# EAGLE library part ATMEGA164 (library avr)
MICROCONTROLLER 16 Kbytes FLASH 1 Kbytes SRAM 512 Bytes EEPROM DUAL USART 8-channel 10 bit ADC
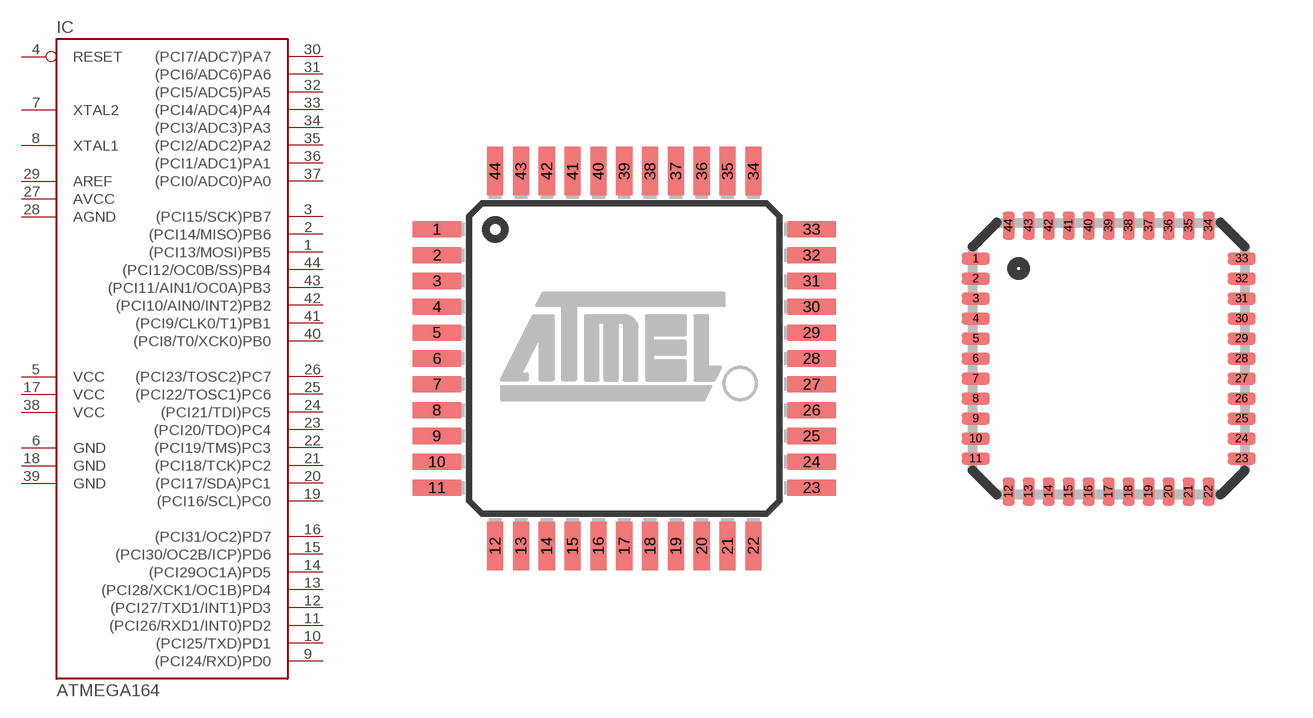
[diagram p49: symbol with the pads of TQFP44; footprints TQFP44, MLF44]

Designator prefix IC

## ATMEGA164-20A, ATMEGA164V-10A  [TQFP44]
1  (PCI13/MOSI)PB5
2  (PCI14/MISO)PB6
3  (PCI15/SCK)PB7
4  RESET  in
5  VCC  pwr
6  GND  pwr
7  XTAL2
8  XTAL1
9  (PCI24/RXD)PD0
10  (PCI25/TXD)PD1
11  (PCI26/RXD1/INT0)PD2
12  (PCI27/TXD1/INT1)PD3
13  (PCI28/XCK1/OC1B)PD4
14  (PCI29OC1A)PD5
15  (PCI30/OC2B/ICP)PD6
16  (PCI31/OC2)PD7
17  VCC  pwr
18  GND  pwr
19  (PCI16/SCL)PC0
20  (PCI17/SDA)PC1
21  (PCI18/TCK)PC2
22  (PCI19/TMS)PC3
23  (PCI20/TDO)PC4
24  (PCI21/TDI)PC5
25  (PCI22/TOSC1)PC6
26  (PCI23/TOSC2)PC7
27  AVCC  pwr
28  AGND  pwr
29  AREF  pwr
30  (PCI7/ADC7)PA7
31  (PCI6/ADC6)PA6
32  (PCI5/ADC5)PA5
33  (PCI4/ADC4)PA4
34  (PCI3/ADC3)PA3
35  (PCI2/ADC2)PA2
36  (PCI1/ADC1)PA1
37  (PCI0/ADC0)PA0
38  VCC  pwr
39  GND  pwr
40  (PCI8/T0/XCK0)PB0
41  (PCI9/CLK0/T1)PB1
42  (PCI10/AIN0/INT2)PB2
43  (PCI11/AIN1/OC0A)PB3
44  (PCI12/OC0B/SS)PB4

## ATMEGA164-20M, ATMEGA164V-10M  [MLF44]
Pads as for TQFP44

## Footprint TQFP44 (pad centres in mm)
Thin Plasic Quad Flat Package
smd 1.5 x 0.5: 1 -5.8,4; 2 -5.8,3.2; 3 -5.8,2.4; 4 -5.8,1.6; 5 -5.8,0.8; 6 -5.8,0; 7 -5.8,-0.8; 8 -5.8,-1.6; 9 -5.8,-2.4; 10 -5.8,-3.2; 11 -5.8,-4; 23 5.8,-4; 24 5.8,-3.2; 25 5.8,-2.4; 26 5.8,-1.6; 27 5.8,-0.8; 28 5.8,0; 29 5.8,0.8; 30 5.8,1.6; 31 5.8,2.4; 32 5.8,3.2; 33 5.8,4
smd 0.5 x 1.5: 12 -4,-5.8; 13 -3.2,-5.8; 14 -2.4,-5.8; 15 -1.6,-5.8; 16 -0.8,-5.8; 17 0,-5.8; 18 0.8,-5.8; 19 1.6,-5.8; 20 2.4,-5.8; 21 3.2,-5.8; 22 4,-5.8; 34 4,5.8; 35 3.2,5.8; 36 2.4,5.8; 37 1.6,5.8; 38 0.8,5.8; 39 0,5.8; 40 -0.8,5.8; 41 -1.6,5.8; 42 -2.4,5.8; 43 -3.2,5.8; 44 -4,5.8

## Footprint MLF44 (pad centres in mm)
44M1 Micro Lead Frame package (MLF)
smd 0.7 x 0.3: 1 -3.325,2.5; 2 -3.325,2; 3 -3.325,1.5; 4 -3.325,1; 5 -3.325,0.5; 6 -3.325,0; 7 -3.325,-0.5; 8 -3.325,-1; 9 -3.325,-1.5; 10 -3.325,-2; 11 -3.325,-2.5; 23 3.325,-2.5; 24 3.325,-2; 25 3.325,-1.5; 26 3.325,-1; 27 3.325,-0.5; 28 3.325,0; 29 3.325,0.5; 30 3.325,1; 31 3.325,1.5; 32 3.325,2; 33 3.325,2.5
smd 0.3 x 0.7: 12 -2.5,-3.325; 13 -2,-3.325; 14 -1.5,-3.325; 15 -1,-3.325; 16 -0.5,-3.325; 17 0,-3.325; 18 0.5,-3.325; 19 1,-3.325; 20 1.5,-3.325; 21 2,-3.325; 22 2.5,-3.325; 34 2.5,3.325; 35 2,3.325; 36 1.5,3.325; 37 1,3.325; 38 0.5,3.325; 39 0,3.325; 40 -0.5,3.325; 41 -1,3.325; 42 -1.5,3.325; 43 -2,3.325; 44 -2.5,3.325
